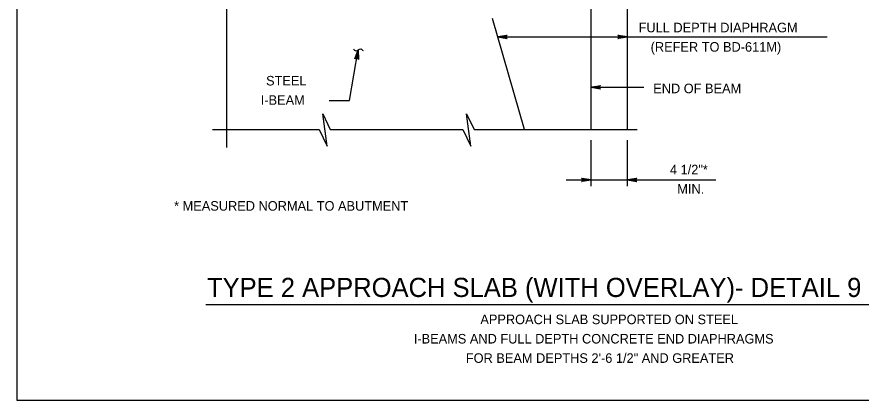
# Model space of a CAD drawing. Extents: x 636530 to 644067, y 294168 to 299122.
# Drawn here: x 639046.8 to 639311.9, y 296559.5 to 296679.7 of the extents above; entities that cross this region are included whole.
import ezdxf

# ---------------------------------------------------------------- set-up
doc = ezdxf.new("R2010")
doc.units = 0
doc.layers.add('1', color=7, linetype='Continuous')

msp = doc.modelspace()

# ---------------------------------------------------------------- linework, layer by layer
at = {"layer": '1'}
for p, q in [((639046.78, 297123.48), (639046.78, 296559.48)), ((639238.55, 296644.38), (639238.55, 296717.13)), ((639112.67, 296690.06), (639112.67, 296638.8)), ((639227.12, 296644.38), (639227.12, 296683.85)), ((639206.21, 296644.38), (639196.14, 296679.27)), ((639197.81, 296673.48), (639301.27, 296673.48)), ((639151.24, 296653.47), (639154.01, 296669.41)), ((639227.12, 296657.65), (639243.69, 296657.65)), ((639144.85, 296653.47), (639151.24, 296653.47)), ((639108.27, 296644.38), (639141.7, 296644.38)), ((639145.21, 296644.38), (639186.84, 296644.38)), ((639190.36, 296644.38), (639241.6, 296644.38)), ((639227.12, 296626.59), (639227.12, 296641.04)), ((639238.55, 296626.59), (639238.55, 296641.04)), ((639219.33, 296628.6), (639266.3, 296628.6)), ((639106.12, 296589.43), (639375.53, 296589.43)), ((639046.78, 296559.48), (639832.78, 296559.48))]:
    msp.add_line(p, q, dxfattribs=at)
for points in [[(639197.81, 296673.48), (639200.79, 296674.04), (639200.68, 296673.96), (639200.56, 296673.88), (639200.5, 296673.78), (639200.44, 296673.68), (639200.43, 296673.58), (639200.41, 296673.48), (639200.43, 296673.38), (639200.44, 296673.28), (639200.5, 296673.18), (639200.56, 296673.08), (639200.68, 296673), (639200.79, 296672.92), (639197.81, 296673.48), (639200.68, 296673), (639200.56, 296673.08), (639197.81, 296673.48), (639200.5, 296673.18), (639200.44, 296673.28), (639197.81, 296673.48), (639200.43, 296673.38), (639200.41, 296673.48), (639197.81, 296673.48), (639200.43, 296673.58), (639200.44, 296673.68), (639197.81, 296673.48), (639200.5, 296673.78), (639200.56, 296673.88), (639197.81, 296673.48), (639200.68, 296673.96)], [(639238.55, 296673.48), (639235.57, 296672.92), (639235.69, 296673), (639235.8, 296673.08), (639235.86, 296673.18), (639235.92, 296673.28), (639235.94, 296673.38), (639235.95, 296673.48), (639235.94, 296673.58), (639235.92, 296673.68), (639235.86, 296673.78), (639235.8, 296673.88), (639235.69, 296673.96), (639235.57, 296674.04), (639238.55, 296673.48), (639235.69, 296673.96), (639235.8, 296673.88), (639238.55, 296673.48), (639235.86, 296673.78), (639235.92, 296673.68), (639238.55, 296673.48), (639235.94, 296673.58), (639235.95, 296673.48), (639238.55, 296673.48), (639235.94, 296673.38), (639235.92, 296673.28), (639238.55, 296673.48), (639235.86, 296673.18), (639235.8, 296673.08), (639238.55, 296673.48), (639235.69, 296673)], [(639154.01, 296669.41), (639154.05, 296666.38), (639154, 296666.5), (639153.94, 296666.63), (639153.85, 296666.71), (639153.76, 296666.78), (639153.66, 296666.82), (639153.57, 296666.85), (639153.47, 296666.85), (639153.37, 296666.85), (639153.26, 296666.81), (639153.15, 296666.77), (639153.05, 296666.67), (639152.95, 296666.57), (639154.01, 296669.41), (639153.05, 296666.67), (639153.15, 296666.77), (639154.01, 296669.41), (639153.26, 296666.81), (639153.37, 296666.85), (639154.01, 296669.41), (639153.47, 296666.85), (639153.57, 296666.85), (639154.01, 296669.41), (639153.66, 296666.82), (639153.76, 296666.78), (639154.01, 296669.41), (639153.85, 296666.71), (639153.94, 296666.63), (639154.01, 296669.41), (639154, 296666.5)], [(639227.12, 296657.65), (639230.11, 296658.21), (639229.99, 296658.13), (639229.88, 296658.05), (639229.82, 296657.95), (639229.76, 296657.85), (639229.74, 296657.75), (639229.72, 296657.65), (639229.74, 296657.55), (639229.76, 296657.45), (639229.82, 296657.35), (639229.88, 296657.25), (639229.99, 296657.17), (639230.11, 296657.09), (639227.12, 296657.65), (639229.99, 296657.17), (639229.88, 296657.25), (639227.12, 296657.65), (639229.82, 296657.35), (639229.76, 296657.45), (639227.12, 296657.65), (639229.74, 296657.55), (639229.72, 296657.65), (639227.12, 296657.65), (639229.74, 296657.75), (639229.76, 296657.85), (639227.12, 296657.65), (639229.82, 296657.95), (639229.88, 296658.05), (639227.12, 296657.65), (639229.99, 296658.13)], [(639141.7, 296644.38), (639144.23, 296639.2), (639142.85, 296649.35), (639145.21, 296644.38)], [(639186.84, 296644.38), (639189.38, 296639.2), (639188, 296649.35), (639190.36, 296644.38)], [(639227.12, 296628.6), (639224.14, 296628.04), (639224.26, 296628.12), (639224.37, 296628.2), (639224.43, 296628.3), (639224.49, 296628.4), (639224.51, 296628.5), (639224.52, 296628.6), (639224.51, 296628.7), (639224.49, 296628.8), (639224.43, 296628.9), (639224.37, 296629), (639224.26, 296629.08), (639224.14, 296629.15), (639227.12, 296628.6), (639224.26, 296629.08), (639224.37, 296629), (639227.12, 296628.6), (639224.43, 296628.9), (639224.49, 296628.8), (639227.12, 296628.6), (639224.51, 296628.7), (639224.52, 296628.6), (639227.12, 296628.6), (639224.51, 296628.5), (639224.49, 296628.4), (639227.12, 296628.6), (639224.43, 296628.3), (639224.37, 296628.2), (639227.12, 296628.6), (639224.26, 296628.12)], [(639238.55, 296628.6), (639241.54, 296629.15), (639241.42, 296629.08), (639241.31, 296629), (639241.25, 296628.9), (639241.19, 296628.8), (639241.17, 296628.7), (639241.15, 296628.6), (639241.17, 296628.5), (639241.19, 296628.4), (639241.25, 296628.3), (639241.31, 296628.2), (639241.42, 296628.12), (639241.54, 296628.04), (639238.55, 296628.6), (639241.42, 296628.12), (639241.31, 296628.2), (639238.55, 296628.6), (639241.25, 296628.3), (639241.19, 296628.4), (639238.55, 296628.6), (639241.17, 296628.5), (639241.15, 296628.6), (639238.55, 296628.6), (639241.17, 296628.7), (639241.19, 296628.8), (639238.55, 296628.6), (639241.25, 296628.9), (639241.31, 296629), (639238.55, 296628.6), (639241.42, 296629.08)]]:
    msp.add_lwpolyline(points, dxfattribs=at)
msp.add_spline([(639152.48, 296669.71), (639153.26, 296669.11), (639154.78, 296669.72), (639155.55, 296669.16)], degree=3, dxfattribs=at)

# ---------------------------------------------------------------- texts
for s, height, p in [('FULL DEPTH DIAPHRAGM', 3, (639242.07, 296674.91)), ('(REFER TO BD-611M)', 3, (639245.84, 296668.84)), ('STEEL', 3, (639125.05, 296658.22)), ('END OF BEAM', 3, (639246.65, 296655.79)), ('I-BEAM', 3, (639123.39, 296652.15)), ('4 1/2"*', 3, (639251.9, 296630.33)), ('MIN.', 3, (639254.2, 296624.26)), ('* MEASURED NORMAL TO ABUTMENT', 3, (639096.16, 296618.93)), ('TYPE 2 APPROACH SLAB (WITH OVERLAY)- DETAIL 9', 6, (639106.49, 296591.84)), ('APPROACH SLAB SUPPORTED ON STEEL', 3, (639192.36, 296583.31)), ('I-BEAMS AND FULL DEPTH CONCRETE END DIAPHRAGMS', 3, (639171.45, 296577.24)), ('FOR BEAM DEPTHS 2\'-6 1/2" AND GREATER', 3, (639187.79, 296571.17))]:
    msp.add_text(s, height=height, dxfattribs=at).set_placement(p)

doc.saveas('drawing.dxf')
